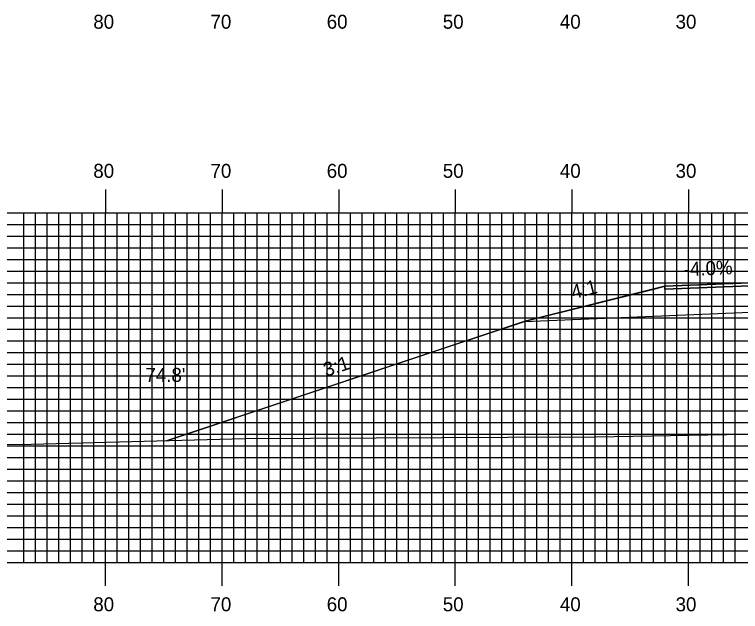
# Model space of a CAD drawing. Extents: x 1757462 to 1757806, y 442591 to 442811.
# Drawn here: x 1757540.3 to 1757602.6, y 442649.4 to 442700.7 of the extents above; entities that cross this region are included whole.
import ezdxf

# ---------------------------------------------------------------- set-up
doc = ezdxf.new("R2010")
doc.units = 0
for name, color, linetype in [('ANNOTATION', 7, 'Continuous'), ('D_Roadway_Centerline', 7, 'Continuous'), ('D_Roadway_Edge_Shoulder', 7, 'Continuous'), ('D_Roadway_SlopeLines', 7, 'Continuous'), ('D_Roadway_SubGrade', 7, 'Continuous'), ('D_Text_Standard', 7, 'Continuous'), ('H_V ANNOTATION', 7, 'Continuous'), ('MAJOR', 7, 'Continuous'), ('MINOR', 7, 'Continuous'), ('S_Roadway_Centerline', 7, 'Continuous')]:
    doc.layers.add(name, color=color, linetype=linetype)

msp = doc.modelspace()

# ---------------------------------------------------------------- linework, layer by layer
at = {"layer": 'D_Roadway_Centerline'}
msp.add_lwpolyline([(1757553.341, 442664.105), (1757577.567, 442672.184), (1757584.046, 442674.345), (1757584.056, 442674.348), (1757584.094, 442674.357), (1757595.268, 442677.152), (1757596.094, 442677.358), (1757604.094, 442677.678), (1757616.109, 442678.177), (1757628.109, 442678.417), (1757640.109, 442678.177), (1757648.109, 442677.857), (1757658.283, 442675.313), (1757660.109, 442674.857), (1757688.68, 442665.333)], dxfattribs=at)
at = {"layer": 'D_Roadway_Edge_Shoulder'}
msp.add_lwpolyline([(1757604.094, 442677.678), (1757596.094, 442677.358), (1757596.094, 442677.108), (1757604.094, 442677.428)], close=True, dxfattribs=at)
at = {"layer": 'D_Roadway_SlopeLines'}
msp.add_lwpolyline([(1757596.094, 442677.358), (1757584.094, 442674.357), (1757553.341, 442664.105)], dxfattribs=at)
at = {"layer": 'D_Roadway_SubGrade'}
msp.add_lwpolyline([(1757604.094, 442677.012), (1757604.094, 442677.428), (1757596.094, 442677.108), (1757596.094, 442677.358), (1757584.046, 442674.345), (1757604.094, 442675.178)], close=True, dxfattribs=at)
at = {"layer": 'MAJOR'}
for p, q in [((1757548.109, 442685.669), (1757548.109, 442683.665)), ((1757558.109, 442685.669), (1757558.109, 442683.665)), ((1757568.109, 442685.669), (1757568.109, 442683.665)), ((1757578.109, 442685.669), (1757578.109, 442683.665)), ((1757588.109, 442685.669), (1757588.109, 442683.665)), ((1757598.109, 442685.669), (1757598.109, 442683.665)), ((1757488.109, 442683.665), (1757768.109, 442683.665)), ((1757488.109, 442683.665), (1757768.109, 442683.665)), ((1757548.109, 442653.665), (1757548.109, 442683.665)), ((1757558.109, 442653.665), (1757558.109, 442683.665)), ((1757568.109, 442653.665), (1757568.109, 442683.665)), ((1757578.109, 442653.665), (1757578.109, 442683.665)), ((1757588.109, 442653.665), (1757588.109, 442683.665)), ((1757598.109, 442653.665), (1757598.109, 442683.665)), ((1757488.109, 442678.665), (1757768.109, 442678.665)), ((1757488.109, 442673.665), (1757768.109, 442673.665)), ((1757488.109, 442668.665), (1757768.109, 442668.665)), ((1757488.109, 442663.665), (1757768.109, 442663.665)), ((1757488.109, 442658.665), (1757768.109, 442658.665)), ((1757488.109, 442653.665), (1757768.109, 442653.665)), ((1757488.109, 442653.665), (1757768.109, 442653.665)), ((1757548.109, 442651.661), (1757548.109, 442653.665)), ((1757558.109, 442651.661), (1757558.109, 442653.665)), ((1757568.109, 442651.661), (1757568.109, 442653.665)), ((1757578.109, 442651.661), (1757578.109, 442653.665)), ((1757588.109, 442651.661), (1757588.109, 442653.665)), ((1757598.109, 442651.661), (1757598.109, 442653.665))]:
    msp.add_line(p, q, dxfattribs=at)
at = {"layer": 'MINOR'}
for p, q in [((1757541.109, 442653.665), (1757541.109, 442683.665)), ((1757542.109, 442653.665), (1757542.109, 442683.665)), ((1757543.109, 442653.665), (1757543.109, 442683.665)), ((1757544.109, 442653.665), (1757544.109, 442683.665)), ((1757545.109, 442653.665), (1757545.109, 442683.665)), ((1757546.109, 442653.665), (1757546.109, 442683.665)), ((1757547.109, 442653.665), (1757547.109, 442683.665)), ((1757549.109, 442653.665), (1757549.109, 442683.665)), ((1757550.109, 442653.665), (1757550.109, 442683.665)), ((1757551.109, 442653.665), (1757551.109, 442683.665)), ((1757552.109, 442653.665), (1757552.109, 442683.665)), ((1757553.109, 442653.665), (1757553.109, 442683.665)), ((1757554.109, 442653.665), (1757554.109, 442683.665)), ((1757555.109, 442653.665), (1757555.109, 442683.665)), ((1757556.109, 442653.665), (1757556.109, 442683.665)), ((1757557.109, 442653.665), (1757557.109, 442683.665)), ((1757559.109, 442653.665), (1757559.109, 442683.665)), ((1757560.109, 442653.665), (1757560.109, 442683.665)), ((1757561.109, 442653.665), (1757561.109, 442683.665)), ((1757562.109, 442653.665), (1757562.109, 442683.665)), ((1757563.109, 442653.665), (1757563.109, 442683.665)), ((1757564.109, 442653.665), (1757564.109, 442683.665)), ((1757565.109, 442653.665), (1757565.109, 442683.665)), ((1757566.109, 442653.665), (1757566.109, 442683.665)), ((1757567.109, 442653.665), (1757567.109, 442683.665)), ((1757569.109, 442653.665), (1757569.109, 442683.665)), ((1757570.109, 442653.665), (1757570.109, 442683.665)), ((1757571.109, 442653.665), (1757571.109, 442683.665)), ((1757572.109, 442653.665), (1757572.109, 442683.665)), ((1757573.109, 442653.665), (1757573.109, 442683.665)), ((1757574.109, 442653.665), (1757574.109, 442683.665)), ((1757575.109, 442653.665), (1757575.109, 442683.665)), ((1757576.109, 442653.665), (1757576.109, 442683.665)), ((1757577.109, 442653.665), (1757577.109, 442683.665)), ((1757579.109, 442653.665), (1757579.109, 442683.665)), ((1757580.109, 442653.665), (1757580.109, 442683.665)), ((1757581.109, 442653.665), (1757581.109, 442683.665)), ((1757582.109, 442653.665), (1757582.109, 442683.665)), ((1757583.109, 442653.665), (1757583.109, 442683.665)), ((1757584.109, 442653.665), (1757584.109, 442683.665)), ((1757585.109, 442653.665), (1757585.109, 442683.665)), ((1757586.109, 442653.665), (1757586.109, 442683.665)), ((1757587.109, 442653.665), (1757587.109, 442683.665)), ((1757589.109, 442653.665), (1757589.109, 442683.665)), ((1757590.109, 442653.665), (1757590.109, 442683.665)), ((1757591.109, 442653.665), (1757591.109, 442683.665)), ((1757592.109, 442653.665), (1757592.109, 442683.665)), ((1757593.109, 442653.665), (1757593.109, 442683.665)), ((1757594.109, 442653.665), (1757594.109, 442683.665)), ((1757595.109, 442653.665), (1757595.109, 442683.665)), ((1757596.109, 442653.665), (1757596.109, 442683.665)), ((1757597.109, 442653.665), (1757597.109, 442683.665)), ((1757599.109, 442653.665), (1757599.109, 442683.665)), ((1757600.109, 442653.665), (1757600.109, 442683.665)), ((1757601.109, 442653.665), (1757601.109, 442683.665)), ((1757602.109, 442653.665), (1757602.109, 442683.665)), ((1757488.109, 442682.665), (1757768.109, 442682.665)), ((1757488.109, 442681.665), (1757768.109, 442681.665)), ((1757488.109, 442680.665), (1757768.109, 442680.665)), ((1757488.109, 442679.665), (1757768.109, 442679.665)), ((1757488.109, 442677.665), (1757768.109, 442677.665)), ((1757488.109, 442676.665), (1757768.109, 442676.665)), ((1757488.109, 442675.665), (1757768.109, 442675.665)), ((1757488.109, 442674.665), (1757768.109, 442674.665)), ((1757488.109, 442672.665), (1757768.109, 442672.665)), ((1757488.109, 442671.665), (1757768.109, 442671.665)), ((1757488.109, 442670.665), (1757768.109, 442670.665)), ((1757488.109, 442669.665), (1757768.109, 442669.665)), ((1757488.109, 442667.665), (1757768.109, 442667.665)), ((1757488.109, 442666.665), (1757768.109, 442666.665)), ((1757488.109, 442665.665), (1757768.109, 442665.665)), ((1757488.109, 442664.665), (1757768.109, 442664.665)), ((1757488.109, 442662.665), (1757768.109, 442662.665)), ((1757488.109, 442661.665), (1757768.109, 442661.665)), ((1757488.109, 442660.665), (1757768.109, 442660.665)), ((1757488.109, 442659.665), (1757768.109, 442659.665)), ((1757488.109, 442657.665), (1757768.109, 442657.665)), ((1757488.109, 442656.665), (1757768.109, 442656.665)), ((1757488.109, 442655.665), (1757768.109, 442655.665)), ((1757488.109, 442654.665), (1757768.109, 442654.665))]:
    msp.add_line(p, q, dxfattribs=at)
at = {"layer": 'S_Roadway_Centerline'}
msp.add_lwpolyline([(1757488.109, 442663.533), (1757499.205, 442663.855), (1757499.477, 442663.857), (1757499.832, 442663.849), (1757508.301, 442663.607), (1757541.719, 442663.795), (1757560.058, 442664.284), (1757582.586, 442664.419), (1757590.13, 442664.451), (1757623.89, 442665.047), (1757628.777, 442665.069), (1757633.54, 442665.217), (1757663.804, 442665.294), (1757670.706, 442665.59), (1757685.162, 442665.374), (1757688.209, 442665.318), (1757699.07, 442665.671)], dxfattribs=at)

# ---------------------------------------------------------------- texts
at = {"layer": 'ANNOTATION'}
for s, rotation, p in [('-4.0%', 2.29421, (1757597.725, 442678.225)), ('4:1', 14.03954, (1757588.216, 442676.25)), ('3:1', 18.44464, (1757567.032, 442669.579))]:
    msp.add_text(s, height=1.2, rotation=rotation, dxfattribs=at).set_placement(p)
at = {"layer": 'D_Text_Standard'}
msp.add_text("74.8'", height=1.2, dxfattribs=at).set_placement((1757551.53, 442669.147))
at = {"layer": 'H_V ANNOTATION'}
for s, p in [('80', (1757547.06, 442699.465)), ('70', (1757557.113, 442699.465)), ('60', (1757567.081, 442699.465)), ('50', (1757577.038, 442699.465)), ('40', (1757587.081, 442699.465)), ('30', (1757597.006, 442699.465)), ('80', (1757547.06, 442686.665)), ('70', (1757557.113, 442686.665)), ('60', (1757567.081, 442686.665)), ('50', (1757577.038, 442686.665)), ('40', (1757587.081, 442686.665)), ('30', (1757597.006, 442686.665)), ('80', (1757547.06, 442649.465)), ('70', (1757557.113, 442649.465)), ('60', (1757567.081, 442649.465)), ('50', (1757577.038, 442649.465)), ('40', (1757587.081, 442649.465)), ('30', (1757597.006, 442649.465))]:
    msp.add_text(s, height=1.2, dxfattribs=at).set_placement(p)

doc.saveas('drawing.dxf')
